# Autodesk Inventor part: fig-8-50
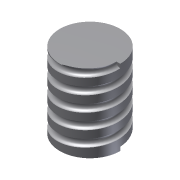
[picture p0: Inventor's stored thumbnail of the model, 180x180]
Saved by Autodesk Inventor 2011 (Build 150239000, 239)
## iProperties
Shininess: 77.0
Length Units: 11269
Angle Units: 11279
Time Units: 11290
Mass Units: 11283
Length Display Precision: 3
Angle Display Precision: 2
Created: 2002-01
Part Number: fig-8-50
Document SubType Name: Modeling
Designer: CADSoft
Density: 1 g/cm^3
Density: 0.0
Volumn: 0.0
Area: 0.0
PropertySet Name: Model Information
Control State: 0
Master: False
Checked Out: False
Author: CADSoft
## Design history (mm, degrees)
sketch "Sketch4"
  geometry: C1 r 20 at (0, 0)
  constraints: 1 centre point
  dimensions: "d44" = 40 diameter of C1
sketch "Sketch2"
  geometry: C1 r 2.5 at (-20, -0.092); 1 further point
  constraints: 1 centre point, 1 other
  dimensions: "d0" = 5 diameter of C1; "d43" = 20 horizontal distance of C1.centre point (0, 0)
extrude "Extrusion2" join sketch "Sketch4" distance "d45" = 50; taper "d46" = 0 deg
coil "Coil6" pitch "d47" = 10; turns "d49" = 5; dims "d48" = 10, "d50" = 0, angle "d51" = 90 deg, angle "d52" = 90 deg, "d53" = 0, "d54" = 0
body "Solid1"
